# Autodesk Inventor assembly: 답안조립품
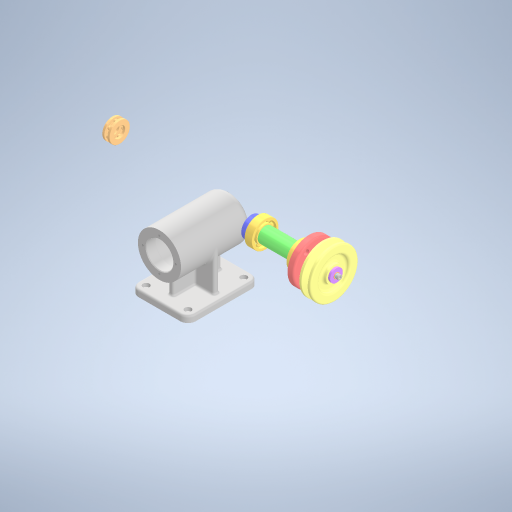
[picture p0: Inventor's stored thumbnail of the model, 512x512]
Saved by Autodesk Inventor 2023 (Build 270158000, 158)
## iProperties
Created: 2026-08
Part Number: 답안조립품
Document SubType Name: Assembly
Designer: 4강의실
Author: 4강의실
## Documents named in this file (14)
- C:\Users\kimgi\Desktop\760803V1001\답안조립품.iam
- C:\Users\kimgi\Desktop\760803V1001\부품.ipt
- C:\Users\kimgi\Desktop\760603V1008\6각 구멍붙이 볼트 M4x12.ipt
- C:\Users\kimgi\Desktop\760603V1008\V 벨트 풀리.ipt
- C:\Users\kimgi\Desktop\760603V1008\깊은 홈 볼 베어링 6004.ipt
- C:\Users\kimgi\Desktop\760603V1008\스러스트 볼 베어링 51202.ipt
- C:\Users\kimgi\Desktop\760603V1008\스프링 와셔 M4.ipt
- C:\Users\kimgi\Desktop\760603V1008\어댑터 슬리브.ipt
- C:\Users\kimgi\Desktop\760603V1008\엔드 캡.ipt
- C:\Users\kimgi\Desktop\760603V1008\오일 실 20 32 5.ipt
- C:\Users\kimgi\Desktop\760603V1008\축.ipt
- C:\Users\kimgi\Desktop\760603V1008\커버.ipt
- C:\Users\kimgi\Desktop\760603V1008\평 와셔 M4.ipt
- C:\Users\kimgi\Desktop\760603V1008\평행 키 5x5x16.ipt
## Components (3 placed, 2 different names)
1. 6각 구멍붙이 볼트 M4x12:1
2. V 벨트 풀리:1
3. 6각 구멍붙이 볼트 M4x12:2
